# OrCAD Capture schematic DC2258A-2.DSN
size A; title: LOW NOISE ADJUSTABLE BIAS GENERATOR; rev: 2; note: DEMO CIRCUIT 2258A
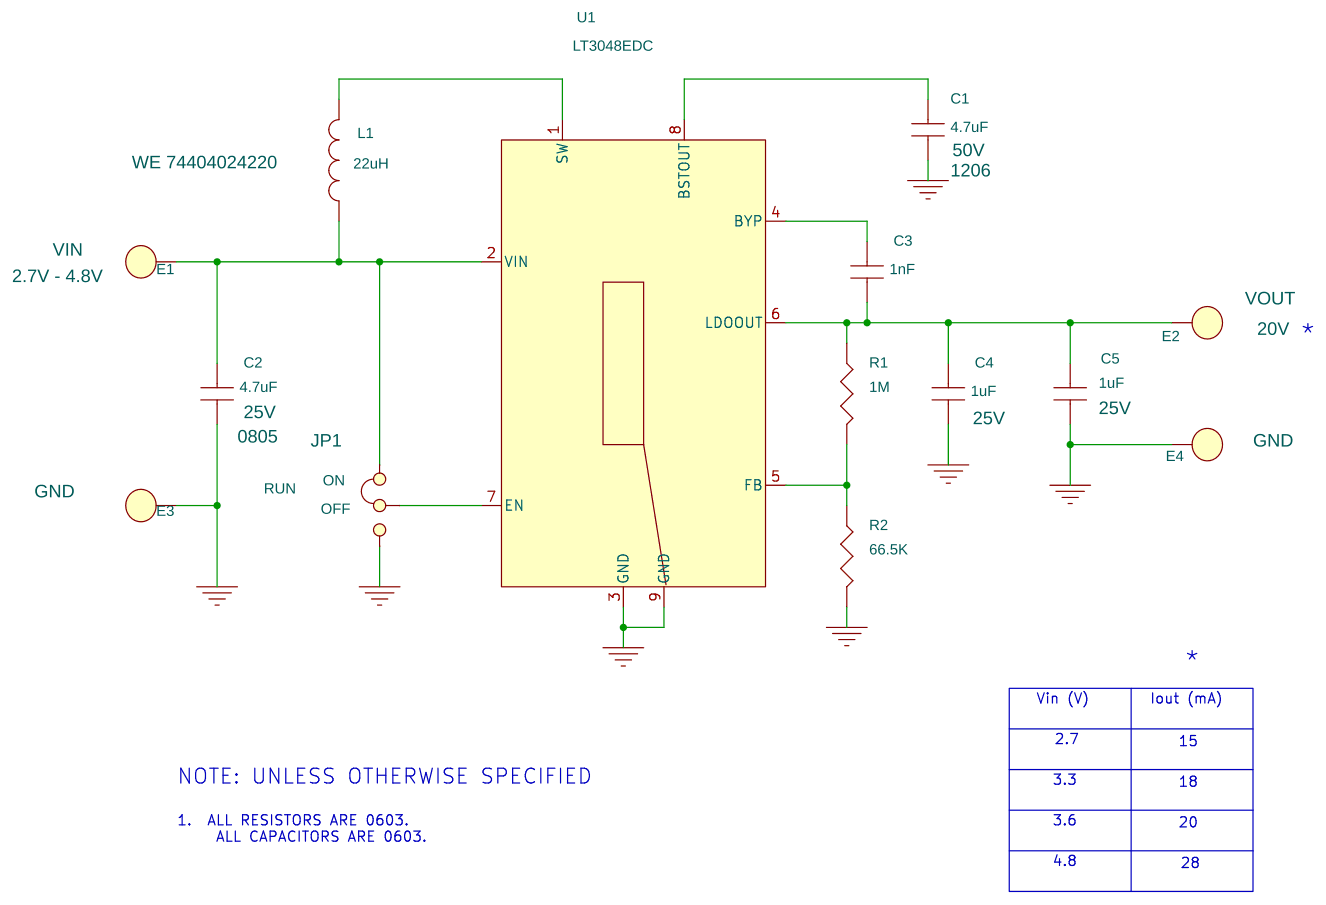
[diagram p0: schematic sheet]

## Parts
C1  4.7uF  [1206]
C2  4.7uF  [0805]
C3  1nF  [0603]
C4  1uF  [0603]
C5  1uF  [0603]
E1  Testpoint  [MM/2501]
E2  Testpoint  [MM/2501]
E3  Testpoint  [MM/2501]
E4  Testpoint  [MM/2501]
JP1  JP3X1/079\NO\12  [JP3X1/079]
L1  22uH  [IND-74404024220]
R1  1M  [0603]
R2  66.5K  [0603]
U1  LT3048EDC  [TDFN-2X2-8P]
XJP1  SHUNT  [NONE]

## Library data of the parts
C1 = CAP0603: CAP, 1206 0.47uF 10% 50V X7R; 1ST PART FIELD: 50V; Part Number: TDK C3216X7R1H474K; Voltage: 6.3V
C2 C4 C5 = CAP0603: CAP, 1206 0.47uF 10% 50V X7R; 1ST PART FIELD: 25V; Part Number: TDK C3216X7R1H474K; Voltage: 6.3V
C3 = CAP0603: CAP, 1206 0.47uF 10% 50V X7R; 1ST PART FIELD: 0402; Part Number: TDK C3216X7R1H474K; Voltage: 6.3V
E1 = MillMax-2501_0: 1ST PART FIELD: VIN; 3RD PART FIELD: 2.7V - 4.8V
E2 = MillMax-2501_0: 1ST PART FIELD: VOUT; 3RD PART FIELD: 20V
E3 = MillMax-2501_0: 1ST PART FIELD: GND; 3RD PART FIELD: GND
E4 = MillMax-2501_0: 1ST PART FIELD: GND; 3RD PART FIELD: 16V, 6mA
JP1 = JP3X1_079_NO_12_3: HEADER, 3PIN 2mm; Field1: RUN; Field2: ON; Field3: OFF; Part Number: SAMTEC TMM-103-02-L-S
L1 = INDUCTOR: 2nd Part Field: WE 74404024220; Part Number: SUMIDA CDRH8D43-6R8
R1 R2 = AAC-0603
U1 = LM7815C_TO3_19: IC, STEP-DOWN SWITCHING REGULATOR; Part Number: LINEAR TECH. LT3693EDD
XJP1 = SHUNT: Part Number: SAMTEC 2SN-BK-G

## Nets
GND1: C1.2 C2.2 C4.2 C5.2 E3.1 E4.1 JP1.1 R2.2 U1.3(GND) U1.9(GND)
N17147318: C3.2 C4.1 C5.1 E2.1 R1.1 U1.6(LDOOUT)
N17147385: C2.1 E1.1 JP1.3 L1.1 U1.2(VIN)
N17147393: C1.1 U1.8(BSTOUT)
N17147443: L1.2 U1.1(SW)
N17147453: JP1.2 U1.7(EN)
N17177675: C3.1 U1.4(BYP)
N17178028: R1.2 R2.1 U1.5(FB)

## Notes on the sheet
- *
- *
- Vin (V)
- Iout (mA)
- 2.7
- 15
- NOTE: UNLESS OTHERWISE SPECIFIED
- 3.3
- 18
- 1.  ALL RESISTORS ARE 0603.
       ALL CAPACITORS ARE 0603.
- 3.6
- 20
- 4.8
- 28
